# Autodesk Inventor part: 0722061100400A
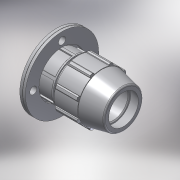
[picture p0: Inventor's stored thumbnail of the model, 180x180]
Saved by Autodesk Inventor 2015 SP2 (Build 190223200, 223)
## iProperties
Created: 2017-02
Part Number: 0722061100400A
Material: PVC-Piping
Description: PLASSON COMPRESSION FLANGE ADAPTOR 110-4"
Document SubType Name: Modeling
Designer: KIM
Mass: 92.6774 g
Surface Area: 199.44 cm^2
Volume: 66.1981 cm^3
Density: 1.4 g/cm^3
Appearance: Smooth - White
Author: KIM
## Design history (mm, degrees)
derived "87220.ipt"
feature "Solid1::87220.ipt"
tag "TaggingFeature1"
body "Solid1"
other parameters: "d4" = 33.57143, "d5" = 75.2, "d7" = 181, "d9" = 33.57143, "d11" = 6.71429, "d12" = 144.8, "d13" = 120 deg, "d15" = 12 deg, "d18" = 5, "d19" = 35 deg, "d20" = 17.5 deg, "d21" = 168.33, "d23" = 0, "d25" = 360 deg, "d27" = 3.62, "d34" = 9.05, "d36" = 0, "d42" = 82.25, "d43" = 5.43, "d46" = 3, "d53" = 2, "d55" = 360 deg, "d70" = 235, "d73" = 19.58333, "d74" = 90 deg, "d75" = 0.3, "d77" = 18, "d80" = 0, "d82" = 360 deg, "d85" = 153.85, "d86" = 144.8, "d87" = 2.44444, "d88" = 0.3, "d93" = 11.75, "d94" = 222, "E_" = 181, "H_" = 235, "l_" = 222, "S_" = 18
